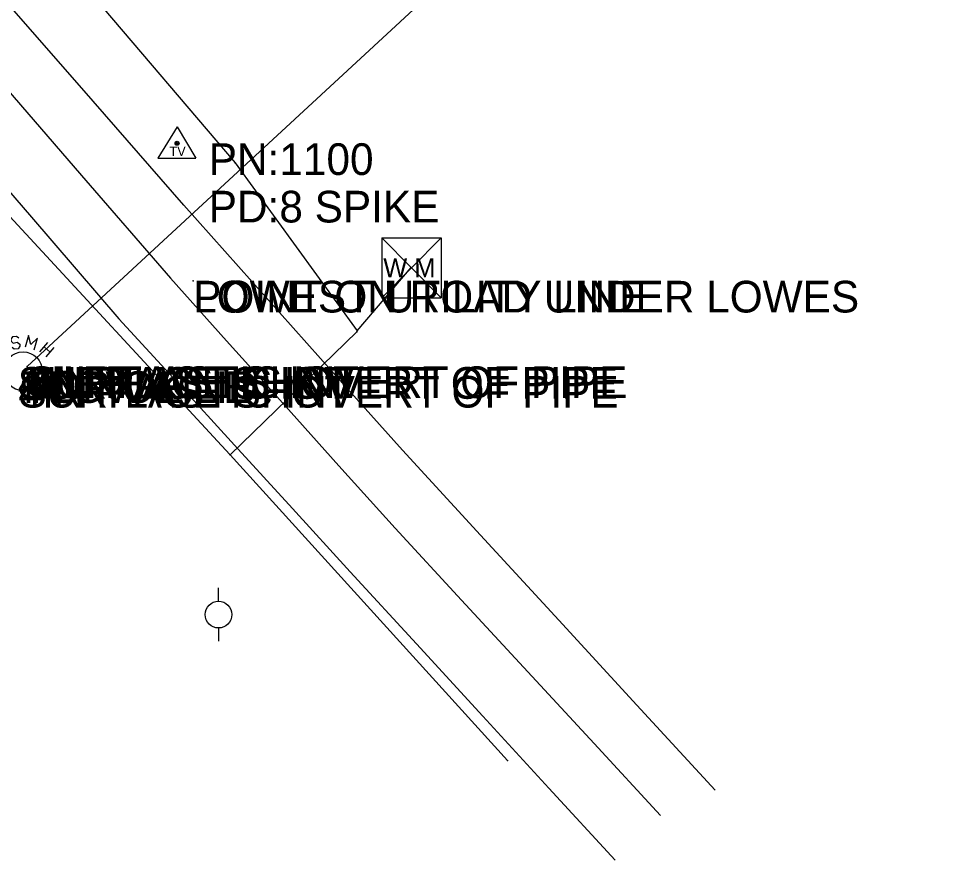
# Model space of a CAD drawing. Extents: x 1660112 to 1662239, y 668919 to 671377.
# Drawn here: x 1661704.2 to 1661851.9, y 669667.7 to 669800.5 of the extents above; entities that cross this region are included whole.
import ezdxf

# ---------------------------------------------------------------- set-up
doc = ezdxf.new("R2010")
doc.units = 0
for name, color, linetype in [('S_EDGE_PAVEMENT', 7, 'Continuous'), ('S_ELECTRIC_UTILITIES_ANNOT', 7, 'Continuous'), ('S_GRD_PT_SYM', 7, 'Continuous'), ('S_MANHOLE_ANNOT', 7, 'Continuous'), ('S_MISC_TOPO_POINT', 7, 'Continuous'), ('S_MSC_PT_SYM', 7, 'Continuous'), ('S_PAVEMENT_CROWN', 7, 'Continuous'), ('S_SANITARY_SEWER', 7, 'Continuous'), ('S_SANITARY_SEWER_ANNOT', 7, 'Continuous'), ('S_SECONDARY_CTL', 7, 'Continuous'), ('S_SECONDARY_CTL_ANNOT', 7, 'Continuous'), ('S_SURVEY_TEXT_ANNOT', 7, 'Continuous'), ('S_UTILITY_POLE', 7, 'Continuous'), ('S_UTL_PT_SYM', 7, 'Continuous'), ('S_WATER_UTILITIES', 7, 'Continuous')]:
    doc.layers.add(name, color=color, linetype=linetype)

msp = doc.modelspace()

# ---------------------------------------------------------------- linework, layer by layer
at = {"layer": 'S_EDGE_PAVEMENT'}
for points in [[(1661814.09, 669678.75), (1661801.76, 669692.17), (1661789.43, 669705.59), (1661777.09, 669719), (1661764.76, 669732.42), (1661756.13, 669742.08), (1661747.5, 669751.75), (1661738.87, 669761.41), (1661730.24, 669771.08), (1661715.94, 669787.51), (1661701.63, 669803.94), (1661687.11, 669820.98), (1661672.59, 669838.02), (1661659.03, 669853.81), (1661645.46, 669869.6), (1661641.26, 669881.81), (1661638.86, 669893.94), (1661637.77, 669899.62)], [(1661587.69, 669853.6), (1661601.46, 669861.14), (1661607.16, 669865.14), (1661611.7, 669864.55), (1661620.99, 669860.83), (1661627.24, 669857.2), (1661632.97, 669852.86), (1661640.64, 669844.85), (1661642.88, 669839.37), (1661651.88, 669829.25), (1661660.88, 669819.13), (1661676.63, 669802.18), (1661692.38, 669785.23), (1661706.18, 669769.2), (1661719.98, 669753.17), (1661729.11, 669743.19), (1661738.25, 669733.2), (1661747.38, 669723.22), (1661756.51, 669713.23), (1661766.96, 669701.85), (1661777.42, 669690.46), (1661787.87, 669679.07), (1661798.32, 669667.68)]]:
    msp.add_lwpolyline(points, dxfattribs=at)
at = {"layer": 'S_GRD_PT_SYM'}
msp.add_lwpolyline([(1661705.52, 669745.65), (1661705.52, 669745.7), (1661705.52, 669745.65), (1661705.47, 669745.65), (1661705.52, 669745.65), (1661705.52, 669745.6), (1661705.52, 669745.65), (1661705.57, 669745.65)], dxfattribs=at)
at = {"layer": 'S_MSC_PT_SYM'}
msp.add_lwpolyline([(1661731.71, 669759.16), (1661731.71, 669759.21), (1661731.71, 669759.16), (1661731.66, 669759.16), (1661731.71, 669759.16), (1661731.71, 669759.11), (1661731.71, 669759.16), (1661731.76, 669759.16)], dxfattribs=at)
at = {"layer": 'S_PAVEMENT_CROWN'}
msp.add_lwpolyline([(1661620.71, 669884.35), (1661629.13, 669874.34), (1661637.54, 669864.33), (1661653.63, 669845.85), (1661669.73, 669827.36), (1661684.9, 669809.66), (1661700.07, 669791.96), (1661714.09, 669775.77), (1661728.11, 669759.57), (1661736.98, 669749.7), (1661745.86, 669739.83), (1661754.73, 669729.96), (1661763.61, 669720.09), (1661774.08, 669708.76), (1661784.55, 669697.43), (1661795.03, 669686.1), (1661805.5, 669674.77)], dxfattribs=at)
at = {"layer": 'S_SANITARY_SEWER'}
for p, q in [((1661863.13, 669891.41), (1661705.52, 669745.65)), ((1661707.51, 669747.95), (1661708.75, 669749.42)), ((1661708.17, 669748.72), (1661709.14, 669747.91)), ((1661709.72, 669748.61), (1661708.48, 669747.14))]:
    msp.add_line(p, q, dxfattribs=at)
for points in [[(1661706.62, 669748.26), (1661707.16, 669750.12), (1661706.11, 669749.11), (1661705.73, 669750.55), (1661705.18, 669748.69)], [(1661704.18, 669750.12), (1661703.83, 669750.39), (1661703.17, 669750.31), (1661702.94, 669749.96), (1661702.98, 669749.65), (1661703.32, 669749.34), (1661703.94, 669749.46), (1661704.33, 669749.15), (1661704.37, 669748.84), (1661704.1, 669748.45), (1661703.48, 669748.38), (1661703.13, 669748.65)]]:
    msp.add_lwpolyline(points, dxfattribs=at)
msp.add_circle((1661704.86, 669744.89), 3.05, dxfattribs=at)
at = {"layer": 'S_SECONDARY_CTL'}
for p, q in [((1661729.17, 669783.48), (1661726.16, 669778.53)), ((1661729.17, 669783.48), (1661732.12, 669778.53)), ((1661726.16, 669778.53), (1661732.12, 669778.53))]:
    msp.add_line(p, q, dxfattribs=at)
for radius in [0.311, 0.183, 0.103]:
    msp.add_circle((1661729.17, 669780.87), radius, dxfattribs=at)
at = {"layer": 'S_UTILITY_POLE'}
for p, q in [((1661735.69, 669708.55), (1661735.69, 669710.67)), ((1661735.69, 669704.33), (1661735.69, 669702.27))]:
    msp.add_line(p, q, dxfattribs=at)
msp.add_circle((1661735.71, 669706.47), 2.11, dxfattribs=at)
at = {"layer": 'S_UTL_PT_SYM'}
for points in [[(1661738.35, 669777.77), (1661738.35, 669777.82), (1661738.35, 669777.77), (1661738.3, 669777.77), (1661738.35, 669777.77), (1661738.35, 669777.72), (1661738.35, 669777.77), (1661738.4, 669777.77)], [(1661766.11, 669761.24), (1661766.11, 669761.29), (1661766.11, 669761.24), (1661766.06, 669761.24), (1661766.11, 669761.24), (1661766.11, 669761.19), (1661766.11, 669761.24), (1661766.16, 669761.24)], [(1661731.71, 669759.16), (1661731.71, 669759.21), (1661731.71, 669759.16), (1661731.66, 669759.16), (1661731.71, 669759.16), (1661731.71, 669759.11), (1661731.71, 669759.16), (1661731.76, 669759.16)], [(1661757.57, 669751.13), (1661757.57, 669751.18), (1661757.57, 669751.13), (1661757.52, 669751.13), (1661757.57, 669751.13), (1661757.57, 669751.08), (1661757.57, 669751.13), (1661757.62, 669751.13)], [(1661757.59, 669751.24), (1661757.59, 669751.29), (1661757.59, 669751.24), (1661757.54, 669751.24), (1661757.59, 669751.24), (1661757.59, 669751.19), (1661757.59, 669751.24), (1661757.64, 669751.24)], [(1661704.86, 669744.89), (1661704.86, 669744.94), (1661704.86, 669744.89), (1661704.81, 669744.89), (1661704.86, 669744.89), (1661704.86, 669744.84), (1661704.86, 669744.89), (1661704.91, 669744.89)], [(1661705.52, 669745.65), (1661705.52, 669745.7), (1661705.52, 669745.65), (1661705.47, 669745.65), (1661705.52, 669745.65), (1661705.52, 669745.6), (1661705.52, 669745.65), (1661705.57, 669745.65)], [(1661737.48, 669731.75), (1661737.48, 669731.8), (1661737.48, 669731.75), (1661737.43, 669731.75), (1661737.48, 669731.75), (1661737.48, 669731.7), (1661737.48, 669731.75), (1661737.53, 669731.75)], [(1661737.54, 669731.67), (1661737.54, 669731.72), (1661737.54, 669731.67), (1661737.49, 669731.67), (1661737.54, 669731.67), (1661737.54, 669731.62), (1661737.54, 669731.67), (1661737.59, 669731.67)], [(1661781.33, 669683.42), (1661781.33, 669683.47), (1661781.33, 669683.42), (1661781.28, 669683.42), (1661781.33, 669683.42), (1661781.33, 669683.37), (1661781.33, 669683.42), (1661781.38, 669683.42)]]:
    msp.add_lwpolyline(points, dxfattribs=at)
at = {"layer": 'S_WATER_UTILITIES'}
for p, q in [((1661706.34, 669815.34), (1661738.35, 669777.77)), ((1661737.48, 669731.75), (1661674.04, 669800.4)), ((1661738.35, 669777.77), (1661757.59, 669751.24)), ((1661761.52, 669765.96), (1661770.86, 669765.96)), ((1661761.52, 669765.96), (1661761.52, 669756.47)), ((1661761.52, 669765.96), (1661770.86, 669756.47)), ((1661770.86, 669765.96), (1661761.52, 669756.47)), ((1661770.86, 669765.96), (1661770.86, 669756.47)), ((1661757.59, 669751.24), (1661766.11, 669761.24)), ((1661761.52, 669756.47), (1661770.86, 669756.47)), ((1661757.57, 669751.13), (1661737.54, 669731.67)), ((1661737.54, 669731.67), (1661781.33, 669683.42))]:
    msp.add_line(p, q, dxfattribs=at)

# ---------------------------------------------------------------- texts
at = {"layer": 'S_ELECTRIC_UTILITIES_ANNOT'}
msp.add_text('LOWEST UTILITY LINE', height=5, dxfattribs=at).set_placement((1661731.71, 669754.16))
at = {"layer": 'S_MANHOLE_ANNOT'}
msp.add_text('FLOW LINE', height=5, dxfattribs=at).set_placement((1661704.86, 669739.89))
at = {"layer": 'S_MISC_TOPO_POINT'}
for p in [(1661704.02, 669740.54), (1661705.52, 669740.65), (1661704.13, 669739.15)]:
    msp.add_text('SURFACE SHOT', height=5, dxfattribs=at).set_placement(p)
at = {"layer": 'S_SANITARY_SEWER_ANNOT'}
for s, p in [('4IN PLASTIC INVERT OF PIPE', (1661704.02, 669740.54)), ('TOP OF LID', (1661704.86, 669739.89)), ('4IN PLASTIC INVERT OF PIPE', (1661705.52, 669740.65)), ('4IN PLASTIC INVERT OF PIPE', (1661704.13, 669739.15))]:
    msp.add_text(s, height=5, dxfattribs=at).set_placement(p)
at = {"layer": 'S_SECONDARY_CTL'}
msp.add_text('TV', height=1.5, rotation=360, dxfattribs=at).set_placement((1661727.97, 669778.86))
at = {"layer": 'S_SECONDARY_CTL_ANNOT'}
for s, p in [('PN:1100', (1661734.17, 669775.87)), ('PD:8 SPIKE', (1661734.17, 669768.37))]:
    msp.add_text(s, height=5, dxfattribs=at).set_placement(p)
at = {"layer": 'S_SURVEY_TEXT_ANNOT'}
msp.add_text('POINT ON ROAD UNDER LOWES', height=5, dxfattribs=at).set_placement((1661731.71, 669754.16))
at = {"layer": 'S_WATER_UTILITIES'}
msp.add_text('W M', height=3, rotation=360, dxfattribs=at).set_placement((1661761.72, 669759.73))

doc.saveas('drawing.dxf')
